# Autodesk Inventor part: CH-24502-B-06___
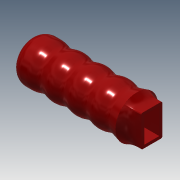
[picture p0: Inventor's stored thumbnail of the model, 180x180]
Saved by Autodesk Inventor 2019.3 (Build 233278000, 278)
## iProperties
Created: 2010-06
Part Number: CH-24502-B-06___
Material: Ogólny
Document SubType Name: Modeling
Designer: CADENGINEERING4
Density: 1 g/cm^3
Appearance: Czerwona
Author: CADENGINEERING4
Revision Number: ANY
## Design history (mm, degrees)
feature "NONE"
node "Bryła1"
